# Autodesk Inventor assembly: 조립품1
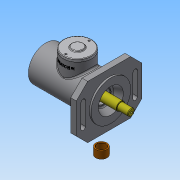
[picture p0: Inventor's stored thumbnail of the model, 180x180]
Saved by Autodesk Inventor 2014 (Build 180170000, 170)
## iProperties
Created: 2017-10
Part Number: 조립품1
Document SubType Name: Assembly
Designer: NET
Author: NET
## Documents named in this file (9)
- C:\Users\NET\Desktop\471007V1026\조립품1.iam
- C:\Users\NET\Desktop\471007V1026\부품1.ipt
- C:\Users\NET\Desktop\471007V1026\탑 커버.ipt
- C:\Users\NET\Desktop\471007V1026\베어링 15 x 35 x 11.ipt
- C:\Users\NET\Desktop\471007V1026\축.ipt
- C:\Users\NET\Desktop\471007V1026\부시1.ipt
- C:\Users\NET\Desktop\471007V1026\부시2.ipt
- C:\Users\NET\Desktop\471007V1026\멈춤링 15 x 1.ipt
- C:\Users\NET\Desktop\471007V1026\멈춤링 35x1.6.ipt
